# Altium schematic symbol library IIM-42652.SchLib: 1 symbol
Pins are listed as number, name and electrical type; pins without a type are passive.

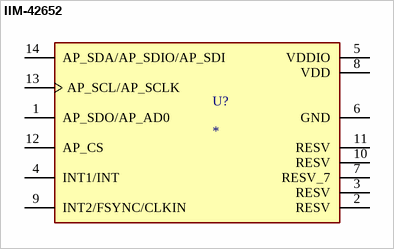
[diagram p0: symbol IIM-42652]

## IIM-42652
designator U?
Accelerometer X, Y, Z Axis Â±2g, 4g, 8g, 16g 6.25Hz ~ 16kHz 14-LGA (2.5x3); MF: TDK InvenSense; MP: IIM-42652
footprint PQFN50P250X300X97-14N
pins: 1 AP_SDO/AP_AD0, 2 RESV, 3 RESV, 4 INT1/INT, 5 VDDIO, 6 GND, 7 RESV_7, 8 VDD, 9 INT2/FSYNC/CLKIN, 10 RESV, 11 RESV, 12 AP_CS, 13 AP_SCL/AP_SCLK, 14 AP_SDA/AP_SDIO/AP_SDI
